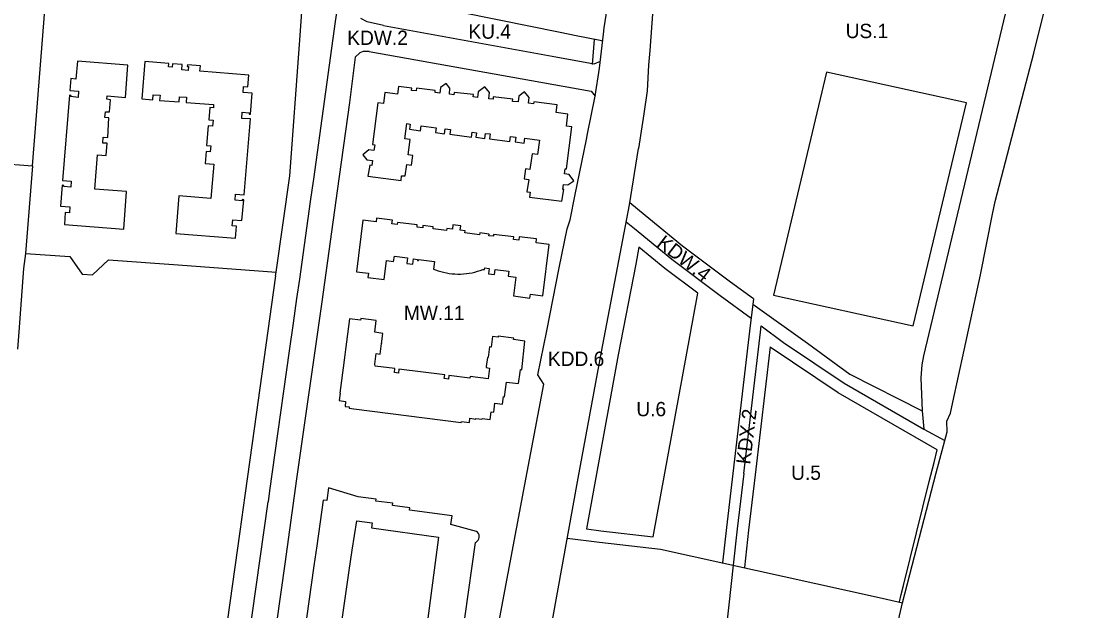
# Model space of a CAD drawing. Extents: x 7427060 to 7429122, y 5545301 to 5546237.
# Drawn here: x 7428222.9 to 7428596.4, y 5545513.7 to 5545719.4 of the extents above; entities that cross this region are included whole.
import ezdxf

# ---------------------------------------------------------------- set-up
doc = ezdxf.new("R2010")
doc.units = 0
for name, color, linetype in [('LIN_Linia Zabudowy Nieprzekraczalna', 7, 'Continuous'), ('LIN_Linia Zabudowy Obowiązujaca', 7, 'Continuous'), ('LIN_Linie Rozgraniczajace', 7, 'Continuous'), ('TXT_Oznaczenia Przeznaczenia', 7, 'Continuous')]:
    doc.layers.add(name, color=color, linetype=linetype)

msp = doc.modelspace()

# ---------------------------------------------------------------- linework, layer by layer
at = {"layer": 'LIN_Linia Zabudowy Nieprzekraczalna'}
for p, q in [((7428504.2, 5545701.66), (7428485.62, 5545623.83)), ((7428553.04, 5545690.89), (7428504.2, 5545701.66)), ((7428534.46, 5545613.06), (7428553.04, 5545690.89)), ((7428447.68, 5545633.08), (7428438.67, 5545640.5)), ((7428459.18, 5545624.47), (7428447.68, 5545633.08)), ((7428443.59, 5545539.46), (7428459.18, 5545624.47)), ((7428485.62, 5545623.83), (7428534.46, 5545613.06))]:
    msp.add_line(p, q, dxfattribs=at)
for points in [[(7428422.48, 5545704.35), (7428423.13, 5545713.06)], [(7428438.67, 5545640.5), (7428437.55, 5545634.66), (7428431.44, 5545602.94), (7428423.32, 5545558.85), (7428420.32, 5545542.16)], [(7428484.53, 5545605.75), (7428479.24, 5545561.09)], [(7428542.79, 5545569.77), (7428508.24, 5545589.69), (7428484.51, 5545605.6)], [(7428529.64, 5545516.66), (7428530.27, 5545519.26), (7428531.06, 5545522.44), (7428533.39, 5545531.8), (7428540.06, 5545558.69), (7428541.75, 5545565.37), (7428542.79, 5545569.77)], [(7428479.24, 5545561.09), (7428476.95, 5545541.76), (7428475.48, 5545528.65)], [(7428420.32, 5545542.16), (7428425.34, 5545541.55), (7428443.59, 5545539.46)]]:
    msp.add_lwpolyline(points, dxfattribs=at)
at = {"layer": 'LIN_Linia Zabudowy Obowiązujaca'}
for p, q in [((7428336.14, 5545604.8), (7428335.66, 5545601.12)), ((7428346.44, 5545599.75), (7428346.92, 5545603.41)), ((7428346.92, 5545603.41), (7428348.25, 5545603.24)), ((7428335.66, 5545601.12), (7428334.18, 5545589.62)), ((7428326.1, 5545536.27), (7428325.05, 5545529.27)), ((7428337.46, 5545527.61), (7428338.46, 5545534.78))]:
    msp.add_line(p, q, dxfattribs=at)
for points in [[(7428242.52, 5545705.54), (7428242.01, 5545699.25), (7428240.22, 5545699.39), (7428239.89, 5545695.28), (7428242.94, 5545695.04), (7428242.73, 5545692.86), (7428240.24, 5545693.1), (7428240.28, 5545693.52), (7428239.76, 5545693.57), (7428237.35, 5545663.87), (7428240.37, 5545663.62), (7428240.22, 5545661.51), (7428237.72, 5545661.69), (7428237.75, 5545662.11), (7428237.23, 5545662.15), (7428236.63, 5545654.85), (7428239.89, 5545654.58), (7428239.73, 5545652.59), (7428238.29, 5545652.69), (7428237.99, 5545648.44), (7428258.68, 5545646.89), (7428259.65, 5545659.94), (7428248.59, 5545660.78), (7428249.48, 5545672.82), (7428252.57, 5545672.6), (7428252.87, 5545676.81), (7428251.42, 5545676.89), (7428251.56, 5545678.96), (7428253.1, 5545678.88), (7428253.55, 5545685.71), (7428252.14, 5545685.78), (7428252.28, 5545687.85), (7428253.77, 5545687.77), (7428254.05, 5545692.05), (7428252.81, 5545692.17), (7428252.91, 5545693.37), (7428259.27, 5545692.79), (7428260.18, 5545704.1)], [(7428266.08, 5545705.39), (7428265.01, 5545692.29), (7428268.82, 5545691.97), (7428268.93, 5545693.78), (7428271.4, 5545693.62), (7428271.24, 5545691.8), (7428278.1, 5545691.26), (7428278.19, 5545693.08), (7428280.62, 5545692.9), (7428280.48, 5545691.09), (7428290.11, 5545690.4), (7428290.01, 5545689.19), (7428288.72, 5545689.3), (7428288.38, 5545684.96), (7428289.89, 5545684.84), (7428289.75, 5545682.79), (7428288.24, 5545682.9), (7428287.65, 5545676.07), (7428289.11, 5545675.96), (7428288.94, 5545673.89), (7428287.46, 5545673.99), (7428287.13, 5545669.8), (7428290.18, 5545669.58), (7428289.17, 5545657.55), (7428277.96, 5545658.44), (7428276.89, 5545645.33), (7428297.75, 5545643.68), (7428298.06, 5545647.88), (7428296.63, 5545647.96), (7428296.75, 5545650.08), (7428299.99, 5545649.84), (7428300.6, 5545657.13), (7428300.08, 5545657.17), (7428300.05, 5545656.75), (7428297.6, 5545656.92), (7428297.77, 5545659.03), (7428300.79, 5545658.79), (7428302.92, 5545685.34), (7428299.9, 5545685.51), (7428300.08, 5545687.65), (7428302.54, 5545687.46), (7428302.51, 5545687.04), (7428303.03, 5545687), (7428303.61, 5545694.27), (7428300.37, 5545694.55), (7428300.56, 5545696.62), (7428302.01, 5545696.49), (7428302.39, 5545700.65), (7428285.32, 5545702.02), (7428285.47, 5545703.82), (7428280.92, 5545704.19), (7428280.88, 5545703.68), (7428281.3, 5545703.65), (7428281.2, 5545702.25), (7428279.02, 5545702.42), (7428279.16, 5545704.34), (7428275.73, 5545704.59), (7428275.64, 5545703.36), (7428274.32, 5545703.49), (7428274.43, 5545704.71)], [(7428411.72, 5545656.58), (7428412.42, 5545660.71), (7428412.08, 5545660.73), (7428412.32, 5545662.4), (7428413.83, 5545662.27), (7428415.95, 5545663.7), (7428414.24, 5545665.95), (7428412.65, 5545666.15), (7428412.87, 5545667.94), (7428413.36, 5545667.88), (7428415.19, 5545682.59), (7428413.32, 5545682.84), (7428413.86, 5545686.98), (7428409.74, 5545687.53), (7428410.1, 5545690.25), (7428401.92, 5545691.33), (7428401.79, 5545690.61), (7428400.12, 5545690.8), (7428400.32, 5545692.79), (7428398.65, 5545694.78), (7428396.73, 5545693.32), (7428396.5, 5545691.24), (7428394.53, 5545691.46), (7428394.62, 5545692.26), (7428387.79, 5545693.03), (7428387.69, 5545692.19), (7428386.2, 5545692.35), (7428386.47, 5545694.51), (7428384.8, 5545696.54), (7428382.5, 5545694.74), (7428382.27, 5545692.84), (7428380.8, 5545693.02), (7428380.9, 5545693.81), (7428374.15, 5545694.61), (7428374.05, 5545693.77), (7428372.47, 5545693.96), (7428372.62, 5545696.11), (7428371.37, 5545697.72), (7428369.37, 5545696.29), (7428369.16, 5545694.36), (7428367.46, 5545694.54), (7428367.54, 5545695.3), (7428360.92, 5545696.02), (7428360.82, 5545695.11), (7428359.27, 5545695.28), (7428359.36, 5545696.11), (7428354.62, 5545696.62), (7428354.27, 5545693.94), (7428349.92, 5545694.52), (7428349.41, 5545690.68), (7428347.48, 5545690.94), (7428345.56, 5545676.35), (7428346.36, 5545676.25), (7428346.1, 5545674.32), (7428344.27, 5545674.52), (7428342.16, 5545672.81), (7428343.62, 5545671.09), (7428345.62, 5545670.83), (7428345.39, 5545669.07), (7428344.65, 5545669.17), (7428344, 5545665.38), (7428355.55, 5545663.85), (7428355.74, 5545665.51), (7428357.03, 5545665.41), (7428357.61, 5545669.4), (7428359.24, 5545669.17), (7428359.7, 5545672.6), (7428358.06, 5545672.82), (7428358.78, 5545678.11), (7428356.9, 5545678.37), (7428357.63, 5545683.7), (7428358.8, 5545683.54), (7428358.54, 5545681.71), (7428362.4, 5545681.18), (7428362.64, 5545682.95), (7428367.81, 5545682.25), (7428367.58, 5545680.58), (7428370.77, 5545680.15), (7428371, 5545681.89), (7428372.8, 5545681.64), (7428372.57, 5545679.98), (7428380.13, 5545678.95), (7428380.38, 5545680.73), (7428381.89, 5545680.52), (7428381.68, 5545678.95), (7428384.84, 5545678.52), (7428385.08, 5545680.29), (7428386.67, 5545680.07), (7428386.44, 5545678.38), (7428393.61, 5545677.4), (7428393.85, 5545679.17), (7428395.64, 5545678.92), (7428395.42, 5545677.35), (7428398.59, 5545676.92), (7428398.81, 5545678.56), (7428403.94, 5545677.86), (7428403.26, 5545672.92), (7428401.35, 5545673.18), (7428400.6, 5545667.65), (7428399, 5545667.87), (7428398.53, 5545664.46), (7428400.16, 5545664.23), (7428399.56, 5545659.86), (7428400.69, 5545659.71), (7428400.49, 5545658.05)], [(7428359.94, 5545636.42), (7428361.33, 5545636.23), (7428361.29, 5545635.94), (7428361.65, 5545635.89), (7428361.7, 5545636.28), (7428367.2, 5545635.52), (7428366.92, 5545632.88), (7428367.56, 5545632.63), (7428368.5, 5545632.3), (7428369.46, 5545632.01), (7428370.43, 5545631.77), (7428371.41, 5545631.56), (7428372.4, 5545631.4), (7428373.39, 5545631.28), (7428374.39, 5545631.21), (7428375.39, 5545631.17), (7428376.39, 5545631.18), (7428377.39, 5545631.23), (7428378.38, 5545631.33), (7428379.37, 5545631.47), (7428380.36, 5545631.64), (7428381.33, 5545631.87), (7428382.29, 5545632.14), (7428383.25, 5545632.44), (7428384.18, 5545632.79), (7428384.71, 5545632.73), (7428384.78, 5545633.31), (7428386.29, 5545633.13), (7428386.06, 5545631.22), (7428388.24, 5545630.95), (7428388.47, 5545632.78), (7428393.17, 5545632.2), (7428392.94, 5545630.37), (7428395.61, 5545630.04), (7428394.81, 5545623.5), (7428400.58, 5545622.79), (7428400.75, 5545624.15), (7428405.14, 5545623.61), (7428407.34, 5545641.52), (7428402.71, 5545642.09), (7428402.88, 5545643.42), (7428396.85, 5545644.15), (7428396.71, 5545643.03), (7428394.86, 5545643.26), (7428394.97, 5545644.16), (7428387.89, 5545645.03), (7428387.81, 5545644.34), (7428386.28, 5545644.53), (7428386.36, 5545645.12), (7428383.03, 5545645.53), (7428382.95, 5545644.87), (7428377.88, 5545645.5), (7428377.98, 5545646.3), (7428376.22, 5545646.52), (7428376.4, 5545647.96), (7428373.7, 5545648.29), (7428373.52, 5545646.87), (7428371.57, 5545647.11), (7428371.47, 5545646.33), (7428366.74, 5545646.91), (7428366.84, 5545647.65), (7428363.23, 5545648.09), (7428363.13, 5545647.31), (7428361.14, 5545647.55), (7428361.24, 5545648.38), (7428354.33, 5545649.22), (7428354.24, 5545648.47), (7428352.4, 5545648.7), (7428352.55, 5545649.94), (7428347, 5545650.62), (7428346.85, 5545649.38), (7428342.18, 5545649.96), (7428339.96, 5545631.94), (7428344.18, 5545631.48), (7428344.01, 5545629.93), (7428349.63, 5545629.31), (7428350.53, 5545635.89), (7428352.98, 5545635.55), (7428353.24, 5545637.4), (7428357.8, 5545636.77), (7428357.54, 5545634.87), (7428359.68, 5545634.58)]]:
    msp.add_lwpolyline(points, close=True, dxfattribs=at)
for points in [[(7428348.25, 5545603.24), (7428348.7, 5545606.86), (7428348.76, 5545606.85), (7428349.22, 5545610.46), (7428346.36, 5545610.82), (7428346.88, 5545614.98), (7428341.48, 5545615.7), (7428341.4, 5545615.06), (7428337.54, 5545615.56), (7428336.14, 5545604.8)], [(7428397.2, 5545596.96), (7428397.3, 5545597.81), (7428397.32, 5545597.81), (7428397.72, 5545597.77), (7428398.78, 5545607.73), (7428394.8, 5545608.27), (7428394.94, 5545608.83), (7428389.52, 5545609.51), (7428389.48, 5545609.16), (7428387.52, 5545609.41), (7428387.05, 5545605.64), (7428386.45, 5545605.71), (7428385.99, 5545602.03), (7428385.77, 5545602.05), (7428385.35, 5545598.94), (7428385.28, 5545598.49), (7428386.51, 5545598.33)], [(7428386.05, 5545594.55), (7428379.72, 5545595.38), (7428379.65, 5545594.83), (7428372.3, 5545595.76), (7428372.12, 5545594.49), (7428370.65, 5545594.71), (7428370.84, 5545595.95), (7428354.85, 5545597.98), (7428354.67, 5545596.6), (7428353.23, 5545596.79), (7428353.41, 5545598.17), (7428346.53, 5545599.05), (7428346.44, 5545599.75)], [(7428386.51, 5545598.33), (7428386.51, 5545598.33), (7428386.05, 5545594.55)], [(7428388.36, 5545586.06), (7428390.98, 5545585.74), (7428391.34, 5545588.36), (7428391.7, 5545588.32), (7428392.35, 5545593.43), (7428396.63, 5545592.89), (7428397.2, 5545596.96)], [(7428334.18, 5545589.62), (7428334.33, 5545589.6), (7428333.99, 5545586.98), (7428336.19, 5545586.7), (7428336, 5545584.96), (7428337.5, 5545584.75), (7428337.45, 5545584.36), (7428339.08, 5545584.16), (7428376.62, 5545579.3), (7428376.66, 5545579.64), (7428379.44, 5545579.28), (7428379.63, 5545580.79), (7428381.71, 5545580.52), (7428381.74, 5545580.77), (7428383.83, 5545580.51), (7428383.86, 5545580.76), (7428386.73, 5545580.37), (7428387.08, 5545583.1), (7428387.97, 5545582.99), (7428388.36, 5545586.06)], [(7428374.32, 5545486.19), (7428381.54, 5545537.45), (7428381.78, 5545537.55), (7428382.18, 5545537.85), (7428382.5, 5545538.23), (7428382.74, 5545538.66), (7428382.87, 5545539.15), (7428382.9, 5545539.65), (7428382.8, 5545540.14), (7428382.6, 5545540.6), (7428382.29, 5545540.99), (7428381.91, 5545541.31), (7428373.01, 5545543.72), (7428373.47, 5545546.73), (7428358.51, 5545548.73), (7428358.62, 5545549.55), (7428352.6, 5545550.32), (7428352.7, 5545551.13), (7428346.76, 5545551.89), (7428346.85, 5545552.61), (7428340.62, 5545553.41), (7428330.26, 5545556.48), (7428329.6, 5545552.04), (7428328.31, 5545552.22), (7428326.1, 5545536.27)], [(7428338.46, 5545534.78), (7428340.09, 5545545.01), (7428345.42, 5545544.33)], [(7428345.42, 5545544.33), (7428345.22, 5545542.59), (7428368.68, 5545539.25), (7428361.9, 5545487.97)], [(7428325.05, 5545529.27), (7428320.05, 5545493.53), (7428329.82, 5545492.11), (7428330.06, 5545493.86), (7428333.05, 5545493.44), (7428333.36, 5545493.91), (7428333.63, 5545494.33), (7428333.83, 5545494.79), (7428333.97, 5545495.27), (7428334.05, 5545495.76), (7428334.05, 5545496.26), (7428333.99, 5545496.76), (7428333.85, 5545497.24), (7428333.66, 5545497.7), (7428333.4, 5545498.13), (7428333.28, 5545498.28), (7428337.46, 5545527.61)]]:
    msp.add_lwpolyline(points, dxfattribs=at)
at = {"layer": 'LIN_Linie Rozgraniczajace'}
for p, q in [((7428228.22, 5545686.48), (7428232.09, 5545734.84)), ((7428226.81, 5545668.9), (7428228.22, 5545686.48)), ((7428156.72, 5545674.4), (7428226.81, 5545668.9)), ((7428311.75, 5545630.49), (7428311.93, 5545631.84)), ((7428537.63, 5545583.4), (7428538.23, 5545577.02))]:
    msp.add_line(p, q, dxfattribs=at)
for points in [[(7428311.93, 5545631.84), (7428316.77, 5545665.44), (7428320.07, 5545711.32), (7428320.77, 5545721.01), (7428321.02, 5545724.45), (7428321.26, 5545727.8), (7428321.68, 5545733.6), (7428322.32, 5545742.57), (7428323.1, 5545748.28), (7428325.54, 5545787.29), (7428322.05, 5545810.56), (7428317.04, 5545809.67), (7428307.43, 5545807.94), (7428304.57, 5545824.21), (7428295.03, 5545878.33), (7428290.65, 5545902.51), (7428290.66, 5545903.06)], [(7428445.05, 5545868.61), (7428447.12, 5545878.09), (7428595.29, 5545849.57), (7428596.44, 5545846.87), (7428538.12, 5545602.56), (7428537.53, 5545599.5), (7428537.18, 5545594.94), (7428537.63, 5545583.4)], [(7428448.26, 5545826.9), (7428448.08, 5545814.22), (7428448.49, 5545804.28), (7428448.69, 5545794.28), (7428446.65, 5545766.53), (7428442.42, 5545709.16), (7428442.05, 5545704.04), (7428441.48, 5545695.08)], [(7428344.16, 5545801.75), (7428341.32, 5545781.52), (7428333.55, 5545726.1), (7428332.61, 5545719.37), (7428324.93, 5545664.31), (7428324.51, 5545661.28), (7428323.83, 5545656.49), (7428320.04, 5545629.35), (7428319.1, 5545622.6), (7428317.9, 5545614.05), (7428316.54, 5545604.3), (7428311.51, 5545568.77), (7428309.63, 5545555.44), (7428309.1, 5545551.64)], [(7428516.73, 5545455.86), (7428530.77, 5545516.4), (7428542.51, 5545561.74), (7428546.32, 5545576.07), (7428546.24, 5545579.81), (7428547.53, 5545582.63), (7428548.36, 5545586.44), (7428552.3, 5545604.54), (7428557.97, 5545630.91), (7428562.18, 5545652.07), (7428563.06, 5545656.55), (7428572.49, 5545692.65), (7428576.58, 5545708.32), (7428583.05, 5545734.15)], [(7428426.05, 5545712.47), (7428425.07, 5545712.67), (7428416.79, 5545714.34), (7428411.16, 5545715.48), (7428389.87, 5545719.79), (7428360.39, 5545725.76), (7428348.77, 5545728.11), (7428342.76, 5545729.33)], [(7428380.98, 5545463), (7428398.84, 5545557.64), (7428405.46, 5545592.7), (7428403.36, 5545596.01), (7428406.46, 5545611.39), (7428410.77, 5545633.3), (7428413.63, 5545646.96), (7428414.61, 5545650.08), (7428416.35, 5545658.93), (7428420.33, 5545678.19), (7428420.74, 5545680.17), (7428423.43, 5545693.33), (7428424.94, 5545703.07), (7428426.34, 5545714.96), (7428426.52, 5545717.08), (7428427.52, 5545723.79)], [(7428349.47, 5545717.95), (7428343.73, 5545719.2), (7428341.5, 5545720.4)], [(7428349.47, 5545717.95), (7428409.63, 5545706.97), (7428422.98, 5545704.57), (7428425.23, 5545705.5)], [(7428344.43, 5545708.9), (7428342.35, 5545708.87), (7428341.16, 5545708.35), (7428339.54, 5545706.88), (7428337.52, 5545691.03), (7428333.26, 5545660.2), (7428327.86, 5545621.48), (7428319.08, 5545559.65), (7428314.95, 5545530.02), (7428309.18, 5545488.82), (7428312.62, 5545484.56)], [(7428344.43, 5545708.9), (7428421.95, 5545694.97), (7428423.43, 5545693.33)], [(7428441.48, 5545695.08), (7428440.39, 5545687.16), (7428438.5, 5545674.95)], [(7428392.97, 5545423.8), (7428404.8, 5545489.73), (7428417.42, 5545559.93), (7428425.55, 5545604.05), (7428431.66, 5545635.8), (7428435.42, 5545655.33), (7428438.5, 5545674.95)], [(7428226.81, 5545668.9), (7428224.36, 5545638.35), (7428223.7, 5545633.15), (7428222, 5545611.03), (7428221.53, 5545604.88)], [(7428478.64, 5545622.5), (7428470.67, 5545628.37), (7428453.86, 5545640.95), (7428442.16, 5545650.58), (7428440.88, 5545651.63), (7428435.53, 5545656.03)], [(7428477.84, 5545615.64), (7428467.09, 5545623.55), (7428450.15, 5545636.23), (7428438.35, 5545645.94), (7428437.07, 5545646.99), (7428434.26, 5545649.3)], [(7428224.36, 5545638.35), (7428239.86, 5545637.3), (7428244.2, 5545631.11), (7428247.76, 5545630.88), (7428253.41, 5545636.14), (7428277.73, 5545634.34), (7428308.92, 5545632.04), (7428311.93, 5545631.84)], [(7428311.75, 5545630.49), (7428303.59, 5545572.14), (7428301.03, 5545553.81), (7428299.2, 5545541.28), (7428289.56, 5545472.35), (7428297.89, 5545471.68)], [(7428478.64, 5545622.5), (7428477.33, 5545611.26), (7428469.21, 5545542.66), (7428467.82, 5545530.35)], [(7428478.42, 5545620.65), (7428497.54, 5545606.98), (7428512.39, 5545596.23), (7428537.63, 5545583.4)], [(7428475.27, 5545561.56), (7428481.1, 5545610.82), (7428481.36, 5545613.05), (7428489.15, 5545607.31), (7428510.36, 5545593.09), (7428538.23, 5545577.02), (7428545.5, 5545572.99)], [(7428475.27, 5545561.56), (7428472.98, 5545542.22), (7428471.55, 5545529.52), (7428464.57, 5545465.61), (7428463.5, 5545455.77), (7428460.68, 5545429.92), (7428462.27, 5545408.23)], [(7428297.89, 5545471.68), (7428309.1, 5545551.64)], [(7428413.65, 5545538.94), (7428424.87, 5545537.58), (7428446.18, 5545535.14)], [(7428446.18, 5545535.14), (7428522.56, 5545518.22), (7428529.26, 5545516.74), (7428530.77, 5545516.4)]]:
    msp.add_lwpolyline(points, dxfattribs=at)

# ---------------------------------------------------------------- texts
at = {"layer": 'TXT_Oznaczenia Przeznaczenia'}
for s, p in [('KU.4', (7428379.11, 5545713.32)), ('KDD.6', (7428406.87, 5545599.07))]:
    msp.add_text(s, height=5, dxfattribs=at).set_placement(p)
for s, rotation, p in [('US.1', 360, (7428510.87, 5545713.54)), ('KDW.2', 360, (7428336.77, 5545711.16)), ('KDW.4', 322.3522, (7428444.56, 5545641.16)), ('MW.11', 360, (7428356.56, 5545615.09)), ('U.6', 360, (7428437.75, 5545581.51)), ('KDX.2', 83.1022, (7428477.52, 5545564.52)), ('U.5', 360, (7428491.82, 5545559.31))]:
    msp.add_text(s, height=5, rotation=rotation, dxfattribs=at).set_placement(p)

doc.saveas('drawing.dxf')
